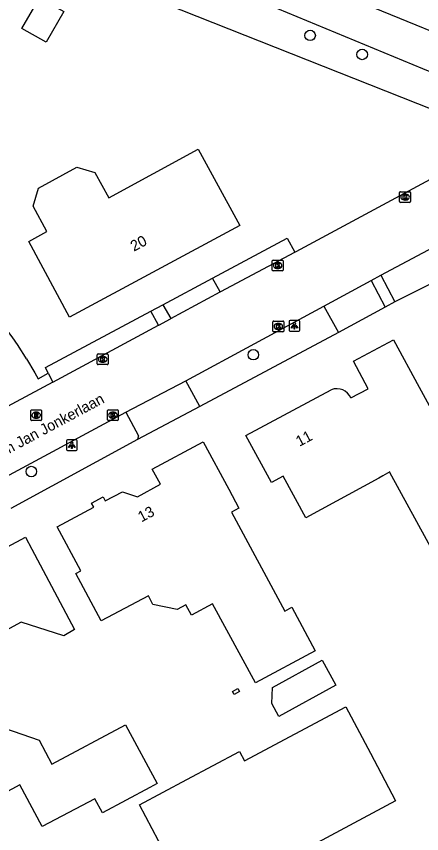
# Model space of a CAD drawing. Extents: x 157321 to 158827, y 386650 to 388532.
# Drawn here: x 158112 to 158149.7, y 387274.1 to 387350.1 of the extents above; entities that cross this region are included whole.
import ezdxf

# ---------------------------------------------------------------- set-up
doc = ezdxf.new("R2010")
doc.units = 0
for name, color, linetype in [('IMGEO_Berm_groen', 7, 'Continuous'), ('IMGEO_Boom', 7, 'Continuous'), ('IMGEO_Fietspad_gesloten', 7, 'Continuous'), ('IMGEO_Groenvoorziening', 7, 'Continuous'), ('IMGEO_Kolk', 7, 'Continuous'), ('IMGEO_Lichtpunt', 7, 'Continuous'), ('IMGEO_Openbare_ruimte_label', 7, 'Continuous'), ('IMGEO_Pand', 7, 'Continuous'), ('IMGEO_Pand_nummerreeks', 7, 'Continuous'), ('IMGEO_Parkeervlak_open', 7, 'Continuous'), ('IMGEO_Rijbaan_lokaal_gesloten', 7, 'Continuous'), ('IMGEO_Rijbaan_lokaal_open', 7, 'Continuous'), ('IMGEO_Rioolput', 7, 'Continuous'), ('IMGEO_Voetpad_halfverhard', 7, 'Continuous'), ('IMGEO_Voetpad_open', 7, 'Continuous')]:
    doc.layers.add(name, color=color, linetype=linetype)

msp = doc.modelspace()

# ---------------------------------------------------------------- linework, layer by layer
at = {"layer": 'IMGEO_Berm_groen'}
msp.add_lwpolyline([(158154.831, 387336.882), (158153.68, 387340.292), (158123.02, 387352.451), (158070.149, 387381.518), (158062.384, 387385.787)], dxfattribs=at)
at = {"layer": 'IMGEO_Boom'}
for centre in [(158139.345, 387348.362), (158144.193, 387346.589), (158134.062, 387318.674), (158113.396, 387307.809)]:
    msp.add_circle(centre, 0.489, dxfattribs=at)
at = {"layer": 'IMGEO_Fietspad_gesloten'}
for points in [[(158075.144, 387386.54), (158119.198, 387362.166), (158123.042, 387360.263), (158125.75, 387359.161), (158134.371, 387355.421), (158178.012, 387337.588)], [(158176.498, 387334.345), (158149.829, 387345.265), (158132.741, 387352.366), (158124.471, 387355.87)]]:
    msp.add_lwpolyline(points, dxfattribs=at)
at = {"layer": 'IMGEO_Groenvoorziening'}
for points in [[(158125.652, 387323.319), (158130.256, 387325.778)], [(158114.975, 387316.969), (158114.71, 387317.476), (158124.519, 387322.714)], [(158141.985, 387320.752), (158129.068, 387313.855)], [(158123.29, 387310.806), (158111.476, 387304.384)]]:
    msp.add_lwpolyline(points, dxfattribs=at)
at = {"layer": 'IMGEO_Kolk'}
for p, q in [((158147.681, 387332.907), (158147.681, 387333.759)), ((158147.756, 387333.833), (158148.608, 387333.833)), ((158148.169, 387333.613), (158148.194, 387333.613)), ((158148.682, 387333.759), (158148.682, 387332.907)), ((158148.608, 387332.833), (158147.756, 387332.833)), ((158148.192, 387333.053), (158148.167, 387333.053)), ((158135.828, 387326.544), (158135.828, 387327.396)), ((158135.903, 387327.47), (158136.755, 387327.47)), ((158136.316, 387327.25), (158136.341, 387327.25)), ((158136.829, 387327.396), (158136.829, 387326.544)), ((158136.755, 387326.47), (158135.903, 387326.47)), ((158136.339, 387326.69), (158136.314, 387326.69)), ((158135.887, 387320.879), (158135.887, 387321.731)), ((158135.962, 387321.805), (158136.814, 387321.805)), ((158136.375, 387321.585), (158136.4, 387321.585)), ((158136.888, 387321.731), (158136.888, 387320.879)), ((158136.814, 387320.805), (158135.962, 387320.805)), ((158136.398, 387321.025), (158136.373, 387321.025)), ((158119.541, 387317.825), (158119.541, 387318.677)), ((158119.616, 387318.751), (158120.468, 387318.751)), ((158120.029, 387318.531), (158120.054, 387318.531)), ((158120.542, 387318.677), (158120.542, 387317.825)), ((158120.468, 387317.751), (158119.616, 387317.751)), ((158120.052, 387317.971), (158120.027, 387317.971)), ((158120.494, 387312.628), (158120.494, 387313.48)), ((158120.569, 387313.554), (158121.421, 387313.554)), ((158120.982, 387313.334), (158121.007, 387313.334)), ((158121.495, 387313.48), (158121.495, 387312.628)), ((158121.421, 387312.554), (158120.569, 387312.554)), ((158121.005, 387312.774), (158120.98, 387312.774))]:
    msp.add_line(p, q, dxfattribs=at)
for points in [[(158147.681, 387332.907), (158147.681, 387333.759)], [(158147.756, 387333.833), (158148.608, 387333.833)], [(158148.682, 387333.759), (158148.682, 387332.907)], [(158148.608, 387332.833), (158147.756, 387332.833)], [(158148.002, 387333.533), (158148.125, 387333.533), (158148.125, 387333.382), (158148.255, 387333.533), (158148.419, 387333.533), (158148.273, 387333.382), (158148.426, 387333.133), (158148.274, 387333.133), (158148.189, 387333.297), (158148.125, 387333.23), (158148.125, 387333.133), (158148.002, 387333.133), (158148.002, 387333.533)], [(158135.828, 387326.544), (158135.828, 387327.396)], [(158135.903, 387327.47), (158136.755, 387327.47)], [(158136.149, 387327.17), (158136.272, 387327.17), (158136.272, 387327.019), (158136.402, 387327.17), (158136.566, 387327.17), (158136.42, 387327.019), (158136.573, 387326.77), (158136.421, 387326.77), (158136.336, 387326.934), (158136.272, 387326.867), (158136.272, 387326.77), (158136.149, 387326.77), (158136.149, 387327.17)], [(158136.829, 387327.396), (158136.829, 387326.544)], [(158136.755, 387326.47), (158135.903, 387326.47)], [(158135.887, 387320.879), (158135.887, 387321.731)], [(158135.962, 387321.805), (158136.814, 387321.805)], [(158136.208, 387321.505), (158136.331, 387321.505), (158136.331, 387321.354), (158136.461, 387321.505), (158136.625, 387321.505), (158136.479, 387321.354), (158136.632, 387321.105), (158136.48, 387321.105), (158136.395, 387321.269), (158136.331, 387321.202), (158136.331, 387321.105), (158136.208, 387321.105), (158136.208, 387321.505)], [(158136.888, 387321.731), (158136.888, 387320.879)], [(158136.814, 387320.805), (158135.962, 387320.805)], [(158119.541, 387317.825), (158119.541, 387318.677)], [(158119.616, 387318.751), (158120.468, 387318.751)], [(158119.862, 387318.451), (158119.985, 387318.451), (158119.985, 387318.3), (158120.115, 387318.451), (158120.279, 387318.451), (158120.133, 387318.3), (158120.286, 387318.051), (158120.134, 387318.051), (158120.049, 387318.215), (158119.985, 387318.148), (158119.985, 387318.051), (158119.862, 387318.051), (158119.862, 387318.451)], [(158120.542, 387318.677), (158120.542, 387317.825)], [(158120.468, 387317.751), (158119.616, 387317.751)], [(158120.494, 387312.628), (158120.494, 387313.48)], [(158120.569, 387313.554), (158121.421, 387313.554)], [(158120.815, 387313.254), (158120.938, 387313.254), (158120.938, 387313.103), (158121.068, 387313.254), (158121.232, 387313.254), (158121.086, 387313.103), (158121.239, 387312.854), (158121.087, 387312.854), (158121.002, 387313.018), (158120.938, 387312.951), (158120.938, 387312.854), (158120.815, 387312.854), (158120.815, 387313.254)], [(158121.495, 387313.48), (158121.495, 387312.628)], [(158121.421, 387312.554), (158120.569, 387312.554)]]:
    msp.add_lwpolyline(points, dxfattribs=at)
for centre, start, end in [((158147.758, 387333.757), 91.55205, 178.44795), ((158147.758, 387333.757), 91.55205, 178.44795), ((158148.606, 387333.757), 1.55205, 88.44795), ((158148.606, 387333.757), 1.55205, 88.44795), ((158147.758, 387332.909), 181.55205, 268.44795), ((158147.758, 387332.909), 181.55205, 268.44795), ((158148.606, 387332.909), 271.55205, 358.44795), ((158148.606, 387332.909), 271.55205, 358.44795), ((158135.905, 387327.394), 91.55205, 178.44795), ((158135.905, 387327.394), 91.55205, 178.44795), ((158136.753, 387327.394), 1.55205, 88.44795), ((158136.753, 387327.394), 1.55205, 88.44795), ((158135.905, 387326.546), 181.55205, 268.44795), ((158135.905, 387326.546), 181.55205, 268.44795), ((158136.753, 387326.546), 271.55205, 358.44795), ((158136.753, 387326.546), 271.55205, 358.44795), ((158135.964, 387321.729), 91.55205, 178.44795), ((158135.964, 387321.729), 91.55205, 178.44795), ((158136.812, 387321.729), 1.55205, 88.44795), ((158136.812, 387321.729), 1.55205, 88.44795), ((158135.964, 387320.881), 181.55205, 268.44795), ((158135.964, 387320.881), 181.55205, 268.44795), ((158136.812, 387320.881), 271.55205, 358.44795), ((158136.812, 387320.881), 271.55205, 358.44795), ((158119.618, 387318.675), 91.55205, 178.44795), ((158119.618, 387318.675), 91.55205, 178.44795), ((158120.466, 387318.675), 1.55205, 88.44795), ((158120.466, 387318.675), 1.55205, 88.44795), ((158119.618, 387317.827), 181.55205, 268.44795), ((158119.618, 387317.827), 181.55205, 268.44795), ((158120.466, 387317.827), 271.55205, 358.44795), ((158120.466, 387317.827), 271.55205, 358.44795), ((158120.571, 387313.478), 91.55205, 178.44795), ((158120.571, 387313.478), 91.55205, 178.44795), ((158121.419, 387313.478), 1.55205, 88.44795), ((158121.419, 387313.478), 1.55205, 88.44795), ((158120.571, 387312.63), 181.55205, 268.44795), ((158120.571, 387312.63), 181.55205, 268.44795), ((158121.419, 387312.63), 271.55205, 358.44795), ((158121.419, 387312.63), 271.55205, 358.44795)]:
    msp.add_arc(centre, 0.0765, start, end, dxfattribs=at)
for centre, major_axis, ratio, start_param, end_param in [((158148.168, 387333.333), (-0.387, 0.002), 0.722429, 4.712389, 7.853982), ((158148.193, 387333.333), (-0.39, 0.002), 0.717154, 1.570796, 4.712389), ((158136.315, 387326.97), (-0.387, 0.002), 0.722429, 4.712389, 7.853982), ((158136.34, 387326.97), (-0.39, 0.002), 0.717154, 1.570796, 4.712389), ((158136.374, 387321.305), (-0.387, 0.002), 0.722429, 4.712389, 7.853982), ((158136.399, 387321.305), (-0.39, 0.002), 0.717154, 1.570796, 4.712389), ((158120.028, 387318.251), (-0.387, 0.002), 0.722429, 4.712389, 7.853982), ((158120.053, 387318.251), (-0.39, 0.002), 0.717154, 1.570796, 4.712389), ((158120.981, 387313.054), (-0.387, 0.002), 0.722429, 4.712389, 7.853982), ((158121.006, 387313.054), (-0.39, 0.002), 0.717154, 1.570796, 4.712389)]:
    msp.add_ellipse(centre, major_axis=major_axis, ratio=ratio, start_param=start_param, end_param=end_param, dxfattribs=at)
at = {"layer": 'IMGEO_Lichtpunt'}
for p, q in [((158137.384, 387321.761), (158137.384, 387320.954)), ((158137.384, 387321.761), (158137.384, 387320.954)), ((158138.286, 387321.856), (158137.478, 387321.856)), ((158138.286, 387321.856), (158137.478, 387321.856)), ((158138.38, 387320.954), (158138.38, 387321.761)), ((158138.38, 387320.954), (158138.38, 387321.761)), ((158137.478, 387320.86), (158138.286, 387320.86)), ((158137.478, 387320.86), (158138.286, 387320.86)), ((158116.663, 387310.663), (158116.663, 387309.856)), ((158116.663, 387310.663), (158116.663, 387309.856)), ((158117.565, 387310.758), (158116.757, 387310.758)), ((158117.565, 387310.758), (158116.757, 387310.758)), ((158117.659, 387309.856), (158117.659, 387310.663)), ((158117.659, 387309.856), (158117.659, 387310.663)), ((158116.757, 387309.762), (158117.565, 387309.762)), ((158116.757, 387309.762), (158117.565, 387309.762))]:
    msp.add_line(p, q, dxfattribs=at)
for points in [[(158137.758, 387321.425), (158137.797, 387321.397), (158137.609, 387321.135), (158137.571, 387321.162), (158137.758, 387321.425)], [(158137.86, 387321.377), (158137.907, 387321.377), (158137.907, 387321.055), (158137.86, 387321.055), (158137.86, 387321.377)], [(158137.97, 387321.397), (158138.008, 387321.424), (158138.195, 387321.162), (158138.156, 387321.134), (158137.97, 387321.397)], [(158117.037, 387310.327), (158117.076, 387310.299), (158116.888, 387310.037), (158116.85, 387310.064), (158117.037, 387310.327)], [(158117.139, 387310.279), (158117.186, 387310.279), (158117.186, 387309.957), (158117.139, 387309.957), (158117.139, 387310.279)], [(158117.249, 387310.299), (158117.287, 387310.326), (158117.474, 387310.064), (158117.435, 387310.036), (158117.249, 387310.299)]]:
    msp.add_lwpolyline(points, dxfattribs=at)
for centre in [(158137.883, 387321.559), (158117.162, 387310.461)]:
    msp.add_circle(centre, 0.0994, dxfattribs=at)
for centre, start, end in [((158137.478, 387321.761), 90, 180), ((158137.478, 387321.761), 90, 180), ((158138.286, 387321.761), 0, 90), ((158138.286, 387321.761), 0, 90), ((158137.478, 387320.954), 180, 270), ((158137.478, 387320.954), 180, 270), ((158138.286, 387320.954), 270, 0), ((158138.286, 387320.954), 270, 360), ((158116.757, 387310.663), 90, 180), ((158116.757, 387310.663), 90, 180), ((158117.565, 387310.663), 0, 90), ((158117.565, 387310.663), 0, 90), ((158116.757, 387309.856), 180, 270), ((158116.757, 387309.856), 180, 270), ((158117.565, 387309.856), 270, 0), ((158117.565, 387309.856), 270, 360)]:
    msp.add_arc(centre, 0.0946, start, end, dxfattribs=at)
at = {"layer": 'IMGEO_Pand'}
for points in [[(158114.156, 387351.867), (158116.42, 387350.577), (158114.793, 387347.72), (158112.529, 387349.01), (158114.156, 387351.867)], [(158117.636, 387336.112), (158119.317, 387335.615), (158120.603, 387333.249), (158128.935, 387337.779), (158130.41, 387335.066), (158132.798, 387330.673), (158116.946, 387322.161), (158113.16, 387329.202), (158114.848, 387330.12), (158113.561, 387332.486), (158114.058, 387334.167), (158117.636, 387336.112)], [(158143.144, 387314.652), (158144.766, 387315.511), (158143.388, 387318.064), (158147.094, 387320.052), (158149.492, 387315.665), (158155.619, 387304.455), (158156.69, 387302.496), (158151.259, 387299.527), (158150.188, 387301.486), (158146.779, 387307.725)], [(158146.779, 387307.725), (158146.764, 387307.774), (158146.121, 387307.423), (158145.736, 387307.212), (158138.942, 387303.499), (158136.825, 387307.373), (158135.757, 387306.789), (158133.371, 387311.154), (158141.322, 387315.423)], [(158139.829, 387291.147), (158134.258, 387288.156), (158130.275, 387295.529), (158128.301, 387294.47), (158127.783, 387295.429), (158126.985, 387294.998), (158124.722, 387295.461), (158124.296, 387296.25), (158119.894, 387293.925), (158117.53, 387298.33), (158118.016, 387298.591), (158115.819, 387302.684), (158119.209, 387304.503), (158119.008, 387304.879), (158120.093, 387305.459), (158120.277, 387305.078), (158121.894, 387305.915), (158123.289, 387305.468), (158125.437, 387306.627), (158124.658, 387308.037), (158129.403, 387310.573), (158131.767, 387306.168), (158132.712, 387304.408), (158132.043, 387304.05), (158136.99, 387294.833), (158137.658, 387295.192), (158139.829, 387291.147)], [(158109.063, 387299.697), (158112.856, 387301.725), (158113.461, 387300.585), (158115.806, 387296.17), (158117.423, 387293.125), (158116.41, 387292.535)], [(158116.41, 387292.535), (158112.441, 387293.806), (158109.961, 387292.482)], [(158141.739, 387287.958), (158136.442, 387285.048), (158135.78, 387286.253), (158135.835, 387287.748), (158140.458, 387290.289), (158141.739, 387287.958)], [(158132.132, 387287.379), (158132.608, 387287.634), (158132.76, 387287.352), (158132.284, 387287.097), (158132.132, 387287.379)], [(158144.954, 387281.623), (158147.305, 387277.209), (158136.986, 387271.676), (158137.944, 387269.909), (158135.949, 387266.727), (158136.111, 387266.615), (158135.384, 387265.4), (158135.204, 387265.524), (158133.79, 387263.231), (158124.845, 387268.778), (158126.414, 387271.273), (158125.829, 387272.376), (158123.465, 387276.833), (158127.879, 387279.184), (158132.781, 387281.794), (158133.246, 387280.922), (158142.658, 387285.934), (158144.954, 387281.623)], [(158109.174, 387284.553), (158114.128, 387282.841), (158115.301, 387280.604), (158122.166, 387284.265), (158125.104, 387278.795), (158124.421, 387278.43), (158120.012, 387276.071), (158119.299, 387277.4), (158114.408, 387274.81), (158112.329, 387278.683), (158109.673, 387277.25)]]:
    msp.add_lwpolyline(points, dxfattribs=at)
msp.add_arc((158141.831, 387314.088), 1.428, 23.23689, 110.89071, dxfattribs=at)
at = {"layer": 'IMGEO_Parkeervlak_open'}
for points in [[(158130.256, 387325.778), (158137.224, 387329.499), (158137.912, 387328.21)], [(158130.986, 387324.51), (158130.256, 387325.778)]]:
    msp.add_lwpolyline(points, dxfattribs=at)
at = {"layer": 'IMGEO_Rijbaan_lokaal_gesloten'}
for points in [[(158137.912, 387328.21), (158138.054, 387328.286), (158152.584, 387336.084)], [(158145.933, 387326.059), (158152.294, 387329.436)], [(158130.986, 387324.51), (158131.05, 387324.545), (158137.912, 387328.21)], [(158145.038, 387325.584), (158145.933, 387326.059)], [(158140.628, 387323.179), (158145.038, 387325.584)], [(158126.396, 387322.038), (158130.986, 387324.51)], [(158127.766, 387316.252), (158140.628, 387323.179)], [(158115.41, 387316.138), (158125.249, 387321.434)], [(158125.249, 387321.434), (158125.255, 387321.437), (158126.357, 387322.017), (158126.396, 387322.038)], [(158115.41, 387316.138), (158106.867, 387311.556)], [(158122.189, 387313.343), (158127.766, 387316.252)], [(158110.123, 387306.842), (158122.189, 387313.343)]]:
    msp.add_lwpolyline(points, dxfattribs=at)
at = {"layer": 'IMGEO_Rijbaan_lokaal_open'}
for points in [[(158112.964, 387318.282), (158113.72, 387316.995), (158114.027, 387316.433), (158114.975, 387316.969)], [(158114.975, 387316.969), (158115.41, 387316.138)]]:
    msp.add_lwpolyline(points, dxfattribs=at)
msp.add_arc((158083.911, 387300.471), 34.078, 31.51076, 57.98562, dxfattribs=at)
at = {"layer": 'IMGEO_Rioolput'}
for p, q in [((158113.348, 387312.623), (158113.348, 387313.475)), ((158113.423, 387313.549), (158114.275, 387313.549)), ((158113.836, 387313.329), (158113.861, 387313.329)), ((158114.349, 387313.475), (158114.349, 387312.623)), ((158114.275, 387312.549), (158113.423, 387312.549)), ((158113.859, 387312.769), (158113.834, 387312.769))]:
    msp.add_line(p, q, dxfattribs=at)
for points in [[(158113.348, 387312.623), (158113.348, 387313.475)], [(158113.423, 387313.549), (158114.275, 387313.549)], [(158113.937, 387313.247), (158113.685, 387313.249), (158113.685, 387312.849)], [(158113.863, 387313.168), (158113.809, 387313.168), (158113.809, 387313.087)], [(158113.809, 387313.087), (158113.861, 387313.087)], [(158114.349, 387313.475), (158114.349, 387312.623)], [(158114.275, 387312.549), (158113.423, 387312.549)], [(158113.685, 387312.849), (158113.809, 387312.849), (158113.809, 387313.011), (158113.82, 387313.011)], [(158113.867, 387312.982), (158113.938, 387312.849), (158114.078, 387312.849), (158114.013, 387312.975)]]:
    msp.add_lwpolyline(points, dxfattribs=at)
for centre, radius, start, end in [((158113.425, 387313.473), 0.0765, 91.55205, 178.44795), ((158113.425, 387313.473), 0.0765, 91.55205, 178.44795), ((158113.845, 387313.276), 0.19, 274.7715, 282.96867), ((158113.869, 387313.072), 0.0964, 77.00612, 93.18647), ((158113.883, 387313.129), 0.0378, 276.66336, 79.67722), ((158113.936, 387313.137), 0.109, 350.36119, 89.41601), ((158113.934, 387313.137), 0.112, 277.58423, 350.98172), ((158114.273, 387313.473), 0.0765, 1.55205, 88.44795), ((158114.273, 387313.473), 0.0765, 1.55205, 88.44795), ((158113.425, 387312.625), 0.0765, 181.55205, 268.44795), ((158113.425, 387312.625), 0.0765, 181.55205, 268.44795), ((158113.819, 387312.958), 0.0533, 26.02933, 88.69889), ((158113.918, 387312.922), 0.108, 29.51342, 73.79051), ((158114.273, 387312.625), 0.0765, 271.55205, 358.44795), ((158114.273, 387312.625), 0.0765, 271.55205, 358.44795)]:
    msp.add_arc(centre, radius, start, end, dxfattribs=at)
for centre, major_axis, ratio, start_param, end_param in [((158113.835, 387313.049), (-0.387, 0.002), 0.722429, 4.712389, 7.853982), ((158113.86, 387313.049), (-0.39, 0.002), 0.717154, 1.570796, 4.712389)]:
    msp.add_ellipse(centre, major_axis=major_axis, ratio=ratio, start_param=start_param, end_param=end_param, dxfattribs=at)
at = {"layer": 'IMGEO_Voetpad_halfverhard'}
msp.add_lwpolyline([(158147.243, 387323.589), (158146.347, 387323.089)], dxfattribs=at)
at = {"layer": 'IMGEO_Voetpad_open'}
for points in [[(158153.727, 387326.8), (158147.243, 387323.589)], [(158145.933, 387326.059), (158147.243, 387323.589)], [(158145.038, 387325.584), (158146.347, 387323.089)], [(158124.519, 387322.714), (158125.652, 387323.319)], [(158125.652, 387323.319), (158126.396, 387322.038)], [(158140.628, 387323.179), (158141.985, 387320.752)], [(158146.347, 387323.089), (158141.985, 387320.752)], [(158125.249, 387321.434), (158124.519, 387322.714)], [(158129.068, 387313.855), (158127.766, 387316.252)], [(158129.068, 387313.855), (158123.29, 387310.806)], [(158122.189, 387313.343), (158123.369, 387311.127), (158123.29, 387310.806)]]:
    msp.add_lwpolyline(points, dxfattribs=at)

# ---------------------------------------------------------------- texts
at = {"layer": 'IMGEO_Openbare_ruimte_label'}
msp.add_text('Willem Jan Jonkerlaan', height=1, rotation=28.18039, dxfattribs=at).set_placement((158108.432, 387307.908))
at = {"layer": 'IMGEO_Pand_nummerreeks'}
for s, rotation, p in [('20', 28.23433, (158122.954, 387328.247)), ('11', 28.22963, (158138.35, 387310.104)), ('13', 27.64521, (158123.644, 387303.08))]:
    msp.add_text(s, height=1, rotation=rotation, dxfattribs=at).set_placement(p)

doc.saveas('drawing.dxf')
